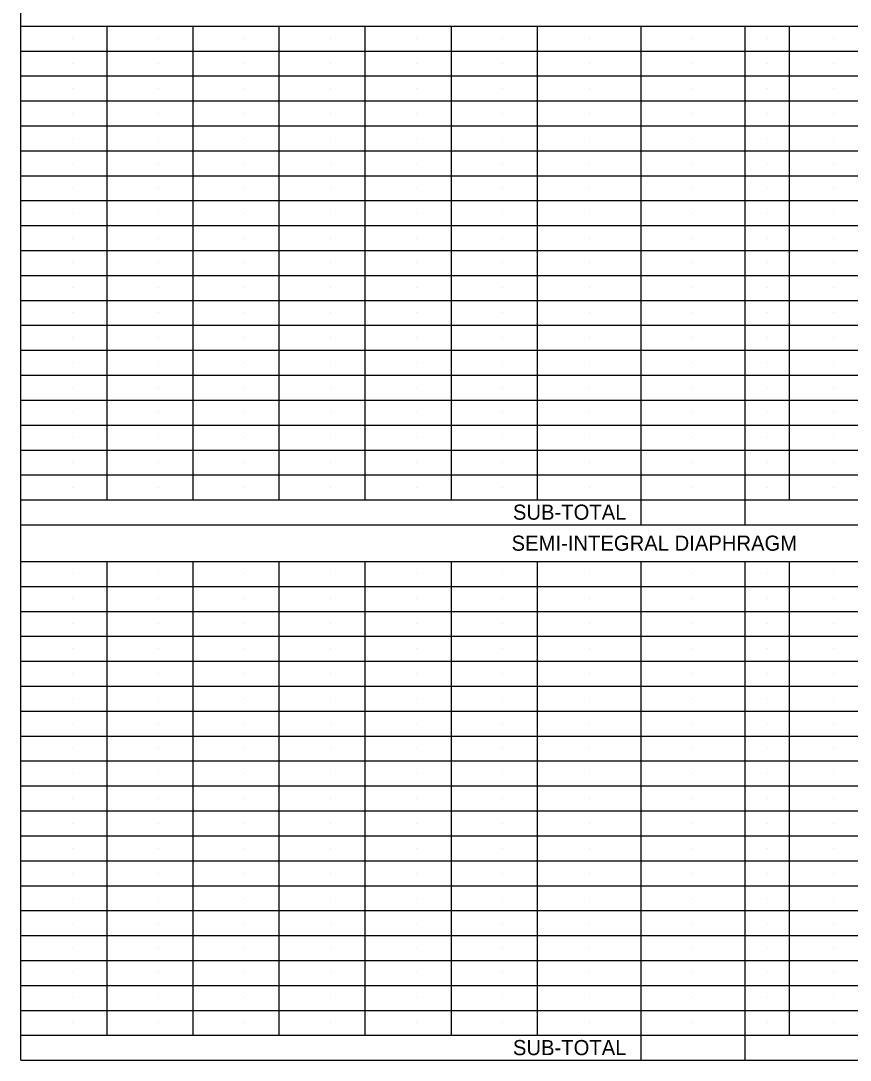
# Model space of a CAD drawing. Extents: x -16.6 to 33.3, y -8.6 to 39.2.
# Drawn here: x -16.64 to -7.32, y 1.28 to 12.95 of the extents above; entities that cross this region are included whole.
import ezdxf

# ---------------------------------------------------------------- set-up
doc = ezdxf.new("R2010")
doc.units = 0
doc.layers.add('BR_X_Beam_Centerline', color=7, linetype='Continuous')

msp = doc.modelspace()

# ---------------------------------------------------------------- linework, layer by layer
at = {"layer": 'BR_X_Beam_Centerline'}
for p, q in [((-16.637, 7.291), (-16.637, 20.715)), ((-16.637, 12.891), (-3.003, 12.891)), ((-15.67, 12.891), (-15.67, 7.571)), ((-14.703, 12.891), (-14.703, 7.571)), ((-13.737, 12.891), (-13.737, 7.571)), ((-12.77, 12.891), (-12.77, 7.571)), ((-11.803, 12.891), (-11.803, 7.571)), ((-10.837, 12.891), (-10.837, 7.571)), ((-9.67, 12.891), (-9.67, 7.291)), ((-8.503, 12.891), (-8.503, 7.291)), ((-8.003, 12.891), (-8.003, 7.571)), ((-16.053, 12.751), (-16.053, 12.751)), ((-15.087, 12.751), (-15.087, 12.751)), ((-14.12, 12.751), (-14.12, 12.751)), ((-13.153, 12.751), (-13.153, 12.751)), ((-12.187, 12.751), (-12.187, 12.751)), ((-11.22, 12.751), (-11.22, 12.751)), ((-10.253, 12.751), (-10.253, 12.751)), ((-9.087, 12.751), (-9.087, 12.751)), ((-8.253, 12.751), (-8.253, 12.751)), ((-7.503, 12.751), (-7.503, 12.751)), ((-16.637, 12.611), (-3.003, 12.611)), ((-16.053, 12.471), (-16.053, 12.471)), ((-15.087, 12.471), (-15.087, 12.471)), ((-14.12, 12.471), (-14.12, 12.471)), ((-13.153, 12.471), (-13.153, 12.471)), ((-12.187, 12.471), (-12.187, 12.471)), ((-11.22, 12.471), (-11.22, 12.471)), ((-10.253, 12.471), (-10.253, 12.471)), ((-9.087, 12.471), (-9.087, 12.471)), ((-8.253, 12.471), (-8.253, 12.471)), ((-7.503, 12.471), (-7.503, 12.471)), ((-16.637, 12.331), (-3.003, 12.331)), ((-16.053, 12.191), (-16.053, 12.191)), ((-15.087, 12.191), (-15.087, 12.191)), ((-14.12, 12.191), (-14.12, 12.191)), ((-13.153, 12.191), (-13.153, 12.191)), ((-12.187, 12.191), (-12.187, 12.191)), ((-11.22, 12.191), (-11.22, 12.191)), ((-10.253, 12.191), (-10.253, 12.191)), ((-9.087, 12.191), (-9.087, 12.191)), ((-8.253, 12.191), (-8.253, 12.191)), ((-7.503, 12.191), (-7.503, 12.191)), ((-16.637, 12.051), (-3.003, 12.051)), ((-16.053, 11.911), (-16.053, 11.911)), ((-15.087, 11.911), (-15.087, 11.911)), ((-14.12, 11.911), (-14.12, 11.911)), ((-13.153, 11.911), (-13.153, 11.911)), ((-12.187, 11.911), (-12.187, 11.911)), ((-11.22, 11.911), (-11.22, 11.911)), ((-10.253, 11.911), (-10.253, 11.911)), ((-9.087, 11.911), (-9.087, 11.911)), ((-8.253, 11.911), (-8.253, 11.911)), ((-7.503, 11.911), (-7.503, 11.911)), ((-16.637, 11.771), (-3.003, 11.771)), ((-16.053, 11.631), (-16.053, 11.631)), ((-15.087, 11.631), (-15.087, 11.631)), ((-14.12, 11.631), (-14.12, 11.631)), ((-13.153, 11.631), (-13.153, 11.631)), ((-12.187, 11.631), (-12.187, 11.631)), ((-11.22, 11.631), (-11.22, 11.631)), ((-10.253, 11.631), (-10.253, 11.631)), ((-9.087, 11.631), (-9.087, 11.631)), ((-8.253, 11.631), (-8.253, 11.631)), ((-7.503, 11.631), (-7.503, 11.631)), ((-16.637, 11.491), (-3.003, 11.491)), ((-16.053, 11.351), (-16.053, 11.351)), ((-15.087, 11.351), (-15.087, 11.351)), ((-14.12, 11.351), (-14.12, 11.351)), ((-13.153, 11.351), (-13.153, 11.351)), ((-12.187, 11.351), (-12.187, 11.351)), ((-11.22, 11.351), (-11.22, 11.351)), ((-10.253, 11.351), (-10.253, 11.351)), ((-9.087, 11.351), (-9.087, 11.351)), ((-8.253, 11.351), (-8.253, 11.351)), ((-7.503, 11.351), (-7.503, 11.351)), ((-16.637, 11.211), (-3.003, 11.211)), ((-16.053, 11.071), (-16.053, 11.071)), ((-15.087, 11.071), (-15.087, 11.071)), ((-14.12, 11.071), (-14.12, 11.071)), ((-13.153, 11.071), (-13.153, 11.071)), ((-12.187, 11.071), (-12.187, 11.071)), ((-11.22, 11.071), (-11.22, 11.071)), ((-10.253, 11.071), (-10.253, 11.071)), ((-9.087, 11.071), (-9.087, 11.071)), ((-8.253, 11.071), (-8.253, 11.071)), ((-7.503, 11.071), (-7.503, 11.071)), ((-16.637, 10.931), (-3.003, 10.931)), ((-16.053, 10.791), (-16.053, 10.791)), ((-15.087, 10.791), (-15.087, 10.791)), ((-14.12, 10.791), (-14.12, 10.791)), ((-13.153, 10.791), (-13.153, 10.791)), ((-12.187, 10.791), (-12.187, 10.791)), ((-11.22, 10.791), (-11.22, 10.791)), ((-10.253, 10.791), (-10.253, 10.791)), ((-9.087, 10.791), (-9.087, 10.791)), ((-8.253, 10.791), (-8.253, 10.791)), ((-7.503, 10.791), (-7.503, 10.791)), ((-16.637, 10.651), (-3.003, 10.651)), ((-16.053, 10.511), (-16.053, 10.511)), ((-15.087, 10.511), (-15.087, 10.511)), ((-14.12, 10.511), (-14.12, 10.511)), ((-13.153, 10.511), (-13.153, 10.511)), ((-12.187, 10.511), (-12.187, 10.511)), ((-11.22, 10.511), (-11.22, 10.511)), ((-10.253, 10.511), (-10.253, 10.511)), ((-9.087, 10.511), (-9.087, 10.511)), ((-8.253, 10.511), (-8.253, 10.511)), ((-7.503, 10.511), (-7.503, 10.511)), ((-16.637, 10.371), (-3.003, 10.371)), ((-16.053, 10.231), (-16.053, 10.231)), ((-15.087, 10.231), (-15.087, 10.231)), ((-14.12, 10.231), (-14.12, 10.231)), ((-13.153, 10.231), (-13.153, 10.231)), ((-12.187, 10.231), (-12.187, 10.231)), ((-11.22, 10.231), (-11.22, 10.231)), ((-10.253, 10.231), (-10.253, 10.231)), ((-9.087, 10.231), (-9.087, 10.231)), ((-8.253, 10.231), (-8.253, 10.231)), ((-7.503, 10.231), (-7.503, 10.231)), ((-16.637, 10.091), (-3.003, 10.091)), ((-16.053, 9.951), (-16.053, 9.951)), ((-15.087, 9.951), (-15.087, 9.951)), ((-14.12, 9.951), (-14.12, 9.951)), ((-13.153, 9.951), (-13.153, 9.951)), ((-12.187, 9.951), (-12.187, 9.951)), ((-11.22, 9.951), (-11.22, 9.951)), ((-10.253, 9.951), (-10.253, 9.951)), ((-9.087, 9.951), (-9.087, 9.951)), ((-8.253, 9.951), (-8.253, 9.951)), ((-7.503, 9.951), (-7.503, 9.951)), ((-16.637, 9.811), (-3.003, 9.811)), ((-16.053, 9.671), (-16.053, 9.671)), ((-15.087, 9.671), (-15.087, 9.671)), ((-14.12, 9.671), (-14.12, 9.671)), ((-13.153, 9.671), (-13.153, 9.671)), ((-12.187, 9.671), (-12.187, 9.671)), ((-11.22, 9.671), (-11.22, 9.671)), ((-10.253, 9.671), (-10.253, 9.671)), ((-9.087, 9.671), (-9.087, 9.671)), ((-8.253, 9.671), (-8.253, 9.671)), ((-7.503, 9.671), (-7.503, 9.671)), ((-16.637, 9.531), (-3.003, 9.531)), ((-16.053, 9.391), (-16.053, 9.391)), ((-15.087, 9.391), (-15.087, 9.391)), ((-14.12, 9.391), (-14.12, 9.391)), ((-13.153, 9.391), (-13.153, 9.391)), ((-12.187, 9.391), (-12.187, 9.391)), ((-11.22, 9.391), (-11.22, 9.391)), ((-10.253, 9.391), (-10.253, 9.391)), ((-9.087, 9.391), (-9.087, 9.391)), ((-8.253, 9.391), (-8.253, 9.391)), ((-7.503, 9.391), (-7.503, 9.391)), ((-16.637, 9.251), (-3.003, 9.251)), ((-16.053, 9.111), (-16.053, 9.111)), ((-15.087, 9.111), (-15.087, 9.111)), ((-14.12, 9.111), (-14.12, 9.111)), ((-13.153, 9.111), (-13.153, 9.111)), ((-12.187, 9.111), (-12.187, 9.111)), ((-11.22, 9.111), (-11.22, 9.111)), ((-10.253, 9.111), (-10.253, 9.111)), ((-9.087, 9.111), (-9.087, 9.111)), ((-8.253, 9.111), (-8.253, 9.111)), ((-7.503, 9.111), (-7.503, 9.111)), ((-16.637, 8.971), (-3.003, 8.971)), ((-16.053, 8.831), (-16.053, 8.831)), ((-15.087, 8.831), (-15.087, 8.831)), ((-14.12, 8.831), (-14.12, 8.831)), ((-13.153, 8.831), (-13.153, 8.831)), ((-12.187, 8.831), (-12.187, 8.831)), ((-11.22, 8.831), (-11.22, 8.831)), ((-10.253, 8.831), (-10.253, 8.831)), ((-9.087, 8.831), (-9.087, 8.831)), ((-8.253, 8.831), (-8.253, 8.831)), ((-7.503, 8.831), (-7.503, 8.831)), ((-16.637, 8.691), (-3.003, 8.691)), ((-16.053, 8.551), (-16.053, 8.551)), ((-15.087, 8.551), (-15.087, 8.551)), ((-14.12, 8.551), (-14.12, 8.551)), ((-13.153, 8.551), (-13.153, 8.551)), ((-12.187, 8.551), (-12.187, 8.551)), ((-11.22, 8.551), (-11.22, 8.551)), ((-10.253, 8.551), (-10.253, 8.551)), ((-9.087, 8.551), (-9.087, 8.551)), ((-8.253, 8.551), (-8.253, 8.551)), ((-7.503, 8.551), (-7.503, 8.551)), ((-16.637, 8.411), (-3.003, 8.411)), ((-16.053, 8.271), (-16.053, 8.271)), ((-15.087, 8.271), (-15.087, 8.271)), ((-14.12, 8.271), (-14.12, 8.271)), ((-13.153, 8.271), (-13.153, 8.271)), ((-12.187, 8.271), (-12.187, 8.271)), ((-11.22, 8.271), (-11.22, 8.271)), ((-10.253, 8.271), (-10.253, 8.271)), ((-9.087, 8.271), (-9.087, 8.271)), ((-8.253, 8.271), (-8.253, 8.271)), ((-7.503, 8.271), (-7.503, 8.271)), ((-16.637, 8.131), (-3.003, 8.131)), ((-16.053, 7.991), (-16.053, 7.991)), ((-15.087, 7.991), (-15.087, 7.991)), ((-14.12, 7.991), (-14.12, 7.991)), ((-13.153, 7.991), (-13.153, 7.991)), ((-12.187, 7.991), (-12.187, 7.991)), ((-11.22, 7.991), (-11.22, 7.991)), ((-10.253, 7.991), (-10.253, 7.991)), ((-9.087, 7.991), (-9.087, 7.991)), ((-8.253, 7.991), (-8.253, 7.991)), ((-7.503, 7.991), (-7.503, 7.991)), ((-16.637, 7.851), (-3.003, 7.851)), ((-16.053, 7.711), (-16.053, 7.711)), ((-15.087, 7.711), (-15.087, 7.711)), ((-14.12, 7.711), (-14.12, 7.711)), ((-13.153, 7.711), (-13.153, 7.711)), ((-12.187, 7.711), (-12.187, 7.711)), ((-11.22, 7.711), (-11.22, 7.711)), ((-10.253, 7.711), (-10.253, 7.711)), ((-9.087, 7.711), (-9.087, 7.711)), ((-8.253, 7.711), (-8.253, 7.711)), ((-7.503, 7.711), (-7.503, 7.711)), ((-16.637, 7.571), (-3.003, 7.571)), ((-16.637, 7.291), (-3.003, 7.291)), ((-16.637, 1.279), (-16.637, 7.291)), ((-9.42, 7.085), (-9.42, 7.085)), ((-16.637, 6.879), (-3.003, 6.879)), ((-15.67, 6.879), (-15.67, 1.559)), ((-14.703, 6.879), (-14.703, 1.559)), ((-13.737, 6.879), (-13.737, 1.559)), ((-12.77, 6.879), (-12.77, 1.559)), ((-11.803, 6.879), (-11.803, 1.559)), ((-10.837, 6.879), (-10.837, 1.559)), ((-9.67, 6.879), (-9.67, 1.279)), ((-8.503, 6.879), (-8.503, 1.279)), ((-8.003, 6.879), (-8.003, 1.559)), ((-16.053, 6.739), (-16.053, 6.739)), ((-15.087, 6.739), (-15.087, 6.739)), ((-14.12, 6.739), (-14.12, 6.739)), ((-13.153, 6.739), (-13.153, 6.739)), ((-12.187, 6.739), (-12.187, 6.739)), ((-11.22, 6.739), (-11.22, 6.739)), ((-10.253, 6.739), (-10.253, 6.739)), ((-9.087, 6.739), (-9.087, 6.739)), ((-8.253, 6.739), (-8.253, 6.739)), ((-7.503, 6.739), (-7.503, 6.739)), ((-16.637, 6.599), (-3.003, 6.599)), ((-16.053, 6.459), (-16.053, 6.459)), ((-15.087, 6.459), (-15.087, 6.459)), ((-14.12, 6.459), (-14.12, 6.459)), ((-13.153, 6.459), (-13.153, 6.459)), ((-12.187, 6.459), (-12.187, 6.459)), ((-11.22, 6.459), (-11.22, 6.459)), ((-10.253, 6.459), (-10.253, 6.459)), ((-9.087, 6.459), (-9.087, 6.459)), ((-8.253, 6.459), (-8.253, 6.459)), ((-7.503, 6.459), (-7.503, 6.459)), ((-16.637, 6.319), (-3.003, 6.319)), ((-16.053, 6.179), (-16.053, 6.179)), ((-15.087, 6.179), (-15.087, 6.179)), ((-14.12, 6.179), (-14.12, 6.179)), ((-13.153, 6.179), (-13.153, 6.179)), ((-12.187, 6.179), (-12.187, 6.179)), ((-11.22, 6.179), (-11.22, 6.179)), ((-10.253, 6.179), (-10.253, 6.179)), ((-9.087, 6.179), (-9.087, 6.179)), ((-8.253, 6.179), (-8.253, 6.179)), ((-7.503, 6.179), (-7.503, 6.179)), ((-16.637, 6.039), (-3.003, 6.039)), ((-16.053, 5.899), (-16.053, 5.899)), ((-15.087, 5.899), (-15.087, 5.899)), ((-14.12, 5.899), (-14.12, 5.899)), ((-13.153, 5.899), (-13.153, 5.899)), ((-12.187, 5.899), (-12.187, 5.899)), ((-11.22, 5.899), (-11.22, 5.899)), ((-10.253, 5.899), (-10.253, 5.899)), ((-9.087, 5.899), (-9.087, 5.899)), ((-8.253, 5.899), (-8.253, 5.899)), ((-7.503, 5.899), (-7.503, 5.899)), ((-16.637, 5.759), (-3.003, 5.759)), ((-16.053, 5.619), (-16.053, 5.619)), ((-15.087, 5.619), (-15.087, 5.619)), ((-14.12, 5.619), (-14.12, 5.619)), ((-13.153, 5.619), (-13.153, 5.619)), ((-12.187, 5.619), (-12.187, 5.619)), ((-11.22, 5.619), (-11.22, 5.619)), ((-10.253, 5.619), (-10.253, 5.619)), ((-9.087, 5.619), (-9.087, 5.619)), ((-8.253, 5.619), (-8.253, 5.619)), ((-7.503, 5.619), (-7.503, 5.619)), ((-16.637, 5.479), (-3.003, 5.479)), ((-16.053, 5.339), (-16.053, 5.339)), ((-15.087, 5.339), (-15.087, 5.339)), ((-14.12, 5.339), (-14.12, 5.339)), ((-13.153, 5.339), (-13.153, 5.339)), ((-12.187, 5.339), (-12.187, 5.339)), ((-11.22, 5.339), (-11.22, 5.339)), ((-10.253, 5.339), (-10.253, 5.339)), ((-9.087, 5.339), (-9.087, 5.339)), ((-8.253, 5.339), (-8.253, 5.339)), ((-7.503, 5.339), (-7.503, 5.339)), ((-16.637, 5.199), (-3.003, 5.199)), ((-16.053, 5.059), (-16.053, 5.059)), ((-15.087, 5.059), (-15.087, 5.059)), ((-14.12, 5.059), (-14.12, 5.059)), ((-13.153, 5.059), (-13.153, 5.059)), ((-12.187, 5.059), (-12.187, 5.059)), ((-11.22, 5.059), (-11.22, 5.059)), ((-10.253, 5.059), (-10.253, 5.059)), ((-9.087, 5.059), (-9.087, 5.059)), ((-8.253, 5.059), (-8.253, 5.059)), ((-7.503, 5.059), (-7.503, 5.059)), ((-16.637, 4.919), (-3.003, 4.919)), ((-16.053, 4.779), (-16.053, 4.779)), ((-15.087, 4.779), (-15.087, 4.779)), ((-14.12, 4.779), (-14.12, 4.779)), ((-13.153, 4.779), (-13.153, 4.779)), ((-12.187, 4.779), (-12.187, 4.779)), ((-11.22, 4.779), (-11.22, 4.779)), ((-10.253, 4.779), (-10.253, 4.779)), ((-9.087, 4.779), (-9.087, 4.779)), ((-8.253, 4.779), (-8.253, 4.779)), ((-7.503, 4.779), (-7.503, 4.779)), ((-16.637, 4.639), (-3.003, 4.639)), ((-16.053, 4.499), (-16.053, 4.499)), ((-15.087, 4.499), (-15.087, 4.499)), ((-14.12, 4.499), (-14.12, 4.499)), ((-13.153, 4.499), (-13.153, 4.499)), ((-12.187, 4.499), (-12.187, 4.499)), ((-11.22, 4.499), (-11.22, 4.499)), ((-10.253, 4.499), (-10.253, 4.499)), ((-9.087, 4.499), (-9.087, 4.499)), ((-8.253, 4.499), (-8.253, 4.499)), ((-7.503, 4.499), (-7.503, 4.499)), ((-16.637, 4.359), (-3.003, 4.359)), ((-16.053, 4.219), (-16.053, 4.219)), ((-15.087, 4.219), (-15.087, 4.219)), ((-14.12, 4.219), (-14.12, 4.219)), ((-13.153, 4.219), (-13.153, 4.219)), ((-12.187, 4.219), (-12.187, 4.219)), ((-11.22, 4.219), (-11.22, 4.219)), ((-10.253, 4.219), (-10.253, 4.219)), ((-9.087, 4.219), (-9.087, 4.219)), ((-8.253, 4.219), (-8.253, 4.219)), ((-7.503, 4.219), (-7.503, 4.219)), ((-16.637, 4.079), (-3.003, 4.079)), ((-16.053, 3.939), (-16.053, 3.939)), ((-15.087, 3.939), (-15.087, 3.939)), ((-14.12, 3.939), (-14.12, 3.939)), ((-13.153, 3.939), (-13.153, 3.939)), ((-12.187, 3.939), (-12.187, 3.939)), ((-11.22, 3.939), (-11.22, 3.939)), ((-10.253, 3.939), (-10.253, 3.939)), ((-9.087, 3.939), (-9.087, 3.939)), ((-8.253, 3.939), (-8.253, 3.939)), ((-7.503, 3.939), (-7.503, 3.939)), ((-16.637, 3.799), (-3.003, 3.799)), ((-16.053, 3.659), (-16.053, 3.659)), ((-15.087, 3.659), (-15.087, 3.659)), ((-14.12, 3.659), (-14.12, 3.659)), ((-13.153, 3.659), (-13.153, 3.659)), ((-12.187, 3.659), (-12.187, 3.659)), ((-11.22, 3.659), (-11.22, 3.659)), ((-10.253, 3.659), (-10.253, 3.659)), ((-9.087, 3.659), (-9.087, 3.659)), ((-8.253, 3.659), (-8.253, 3.659)), ((-7.503, 3.659), (-7.503, 3.659)), ((-16.637, 3.519), (-3.003, 3.519)), ((-16.053, 3.379), (-16.053, 3.379)), ((-15.087, 3.379), (-15.087, 3.379)), ((-14.12, 3.379), (-14.12, 3.379)), ((-13.153, 3.379), (-13.153, 3.379)), ((-12.187, 3.379), (-12.187, 3.379)), ((-11.22, 3.379), (-11.22, 3.379)), ((-10.253, 3.379), (-10.253, 3.379)), ((-9.087, 3.379), (-9.087, 3.379)), ((-8.253, 3.379), (-8.253, 3.379)), ((-7.503, 3.379), (-7.503, 3.379)), ((-16.637, 3.239), (-3.003, 3.239)), ((-16.053, 3.099), (-16.053, 3.099)), ((-15.087, 3.099), (-15.087, 3.099)), ((-14.12, 3.099), (-14.12, 3.099)), ((-13.153, 3.099), (-13.153, 3.099)), ((-12.187, 3.099), (-12.187, 3.099)), ((-11.22, 3.099), (-11.22, 3.099)), ((-10.253, 3.099), (-10.253, 3.099)), ((-9.087, 3.099), (-9.087, 3.099)), ((-8.253, 3.099), (-8.253, 3.099)), ((-7.503, 3.099), (-7.503, 3.099)), ((-16.637, 2.959), (-3.003, 2.959)), ((-16.053, 2.819), (-16.053, 2.819)), ((-15.087, 2.819), (-15.087, 2.819)), ((-14.12, 2.819), (-14.12, 2.819)), ((-13.153, 2.819), (-13.153, 2.819)), ((-12.187, 2.819), (-12.187, 2.819)), ((-11.22, 2.819), (-11.22, 2.819)), ((-10.253, 2.819), (-10.253, 2.819)), ((-9.087, 2.819), (-9.087, 2.819)), ((-8.253, 2.819), (-8.253, 2.819)), ((-7.503, 2.819), (-7.503, 2.819)), ((-16.637, 2.679), (-3.003, 2.679)), ((-16.053, 2.539), (-16.053, 2.539)), ((-15.087, 2.539), (-15.087, 2.539)), ((-14.12, 2.539), (-14.12, 2.539)), ((-13.153, 2.539), (-13.153, 2.539)), ((-12.187, 2.539), (-12.187, 2.539)), ((-11.22, 2.539), (-11.22, 2.539)), ((-10.253, 2.539), (-10.253, 2.539)), ((-9.087, 2.539), (-9.087, 2.539)), ((-8.253, 2.539), (-8.253, 2.539)), ((-7.503, 2.539), (-7.503, 2.539)), ((-16.637, 2.399), (-3.003, 2.399)), ((-16.053, 2.259), (-16.053, 2.259)), ((-15.087, 2.259), (-15.087, 2.259)), ((-14.12, 2.259), (-14.12, 2.259)), ((-13.153, 2.259), (-13.153, 2.259)), ((-12.187, 2.259), (-12.187, 2.259)), ((-11.22, 2.259), (-11.22, 2.259)), ((-10.253, 2.259), (-10.253, 2.259)), ((-9.087, 2.259), (-9.087, 2.259)), ((-8.253, 2.259), (-8.253, 2.259)), ((-7.503, 2.259), (-7.503, 2.259)), ((-16.637, 2.119), (-3.003, 2.119)), ((-16.053, 1.979), (-16.053, 1.979)), ((-15.087, 1.979), (-15.087, 1.979)), ((-14.12, 1.979), (-14.12, 1.979)), ((-13.153, 1.979), (-13.153, 1.979)), ((-12.187, 1.979), (-12.187, 1.979)), ((-11.22, 1.979), (-11.22, 1.979)), ((-10.253, 1.979), (-10.253, 1.979)), ((-9.087, 1.979), (-9.087, 1.979)), ((-8.253, 1.979), (-8.253, 1.979)), ((-7.503, 1.979), (-7.503, 1.979)), ((-16.637, 1.839), (-3.003, 1.839)), ((-16.053, 1.699), (-16.053, 1.699)), ((-15.087, 1.699), (-15.087, 1.699)), ((-14.12, 1.699), (-14.12, 1.699)), ((-13.153, 1.699), (-13.153, 1.699)), ((-12.187, 1.699), (-12.187, 1.699)), ((-11.22, 1.699), (-11.22, 1.699)), ((-10.253, 1.699), (-10.253, 1.699)), ((-9.087, 1.699), (-9.087, 1.699)), ((-8.253, 1.699), (-8.253, 1.699)), ((-7.503, 1.699), (-7.503, 1.699)), ((-16.637, 1.559), (-3.003, 1.559)), ((-16.637, 1.279), (-3.003, 1.279))]:
    msp.add_line(p, q, dxfattribs=at)

# ---------------------------------------------------------------- texts
for s, p in [('SUB-TOTAL', (-11.108, 7.348)), ('SEMI-INTEGRAL DIAPHRAGM', (-11.123, 7)), ('SUB-TOTAL', (-11.108, 1.336))]:
    msp.add_text(s, height=0.17, dxfattribs=at).set_placement(p)

doc.saveas('drawing.dxf')
